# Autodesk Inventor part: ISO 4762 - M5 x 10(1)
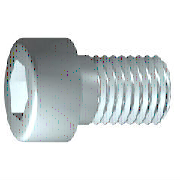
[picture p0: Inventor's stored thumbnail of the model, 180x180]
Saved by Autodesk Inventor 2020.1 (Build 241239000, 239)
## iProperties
Created: 2019-01
Part Number: ISO 4762 - M5 x 10(1)
Material: Edelstahl, 440C
Description: Innensechskantschraube
Document SubType Name: Modeling
Standard: ISO 4762
Designer: lutzd
Standard Revision: Fourth edition 2004-03-01
Standards Organization: ISO
Language: de-DE
Size Designation: M5 x 10
Categories: <MemberInstance><Categories><Category DisplayName="Verbindungselemente" InternalName="e4da775c-781d-43d5-af7c-5136215cf5a6" Mnemonic="FSTN"><Category DisplayNam
Mass: 3.37173 g
Surface Area: 4.31157 cm^2
Volume: 0.435062 cm^3
Density: 7.75 g/cm^3
Appearance: Halbpoliert
IsCustomPart: 0
Author: lutzd
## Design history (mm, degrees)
body "Solid1"
sketch "Skizze1"
  geometry: L1 (-1.167, 0)-(10, 0); L2 (10, 0)-(10, 2.5); L3 (10, 2.5)-(2, 2.5); L4 (2, 2.5)-(1.509, 2.5); L5 (1.509, 2.5)-(0, 2.5); L6 (0, 2.5)-(0, 4.25); L7 (0, 4.25)-(-5, 4.25); L8 (-5, 4.25)-(-5, 2.309); L9 (-5, 2.309)-(-2.5, 2.309); L10 (-2.5, 2.309)-(-1.167, 0); L11 (-8, 0)-(13, 0) reference; L12 (0, -0.85)-(0, 5.1) reference; L13 (2, 2.5)-(0, 2.5)
  constraints: 22 end point, 6 parallel, 2 collinear, 2 perpendicular, 1 horizontal, 1 point on line
  dimensions: "d1" = 8 distance from line of L3.end L2 (= GEL); "d2" = 0.49086 distance of L4.end L3.end (computed from GAL); "d3" = 5 distance between parallel lines of L8 L6 (= KOH); "d4" = 2.5 distance of L8.end L9.end (= INTI); "d5" = 60 deg angle of L10 L1; "d6" = 5 diameter of L3 L1 (= GD); "d7" = 5 diameter of L5 L1 (= BDM); "d8" = 4.6188 diameter of L9 L1 (= 1.1547 x SW); "d9" = 8.5 diameter of L7 L1 (= KOD); "d26" = 10 distance between parallel lines of L12 L2 (= NLG)
workplane "Work Plane1"
fillet "Fillet2" dims "d30" = 0.1 (= R)
revolve "Körper" stored, may be unused: angle "d10" = 90 deg
sketch "Skizze2"
  geometry: L1 (0, -5.95)-(0, 5.95) reference; L2 (-5.95, 0)-(5.95, 0) reference; L3 (2.309, 0)-(1.155, -2); L4 (1.155, -2)-(-1.155, -2); L5 (-1.155, -2)-(-2.309, 0); L6 (-2.309, 0)-(-1.155, 2); L7 (-1.155, 2)-(1.155, 2); L8 (1.155, 2)-(2.309, 0); 2 further points
  constraints: 12 end point, 1 coincident, 1 horizontal alignment, 1 point on line, 12 other
extrude "Loch" join sketch "Skizze2" stored distance "d11" = 10; taper "d12" = 0 deg
fillet "Rundung1" dims "d17" = 0.5 (= RR)
feature "Gewinde" dims "d13" = 8 (= GEL), "d14" = 0
chamfer "Fase1" distance "d15" = 0.49076 (= -0.5 x SPD + 0.5 x GD); stored, may be unused: second distance "d16" = 0.49076 (= GUL), angle "d27" = 45 deg
other parameters: "GD" = 5 [user parameter; used in 2 equation terms], "NLG" = 10 [user parameter; used in 1 equation term], "GEL" = 8 [user parameter; used in 2 equation terms], "KOD" = 8.5 [user parameter; used in 1 equation term], "KOH" = 5 [user parameter; used in 1 equation term], "INTI" = 2.5 [user parameter; used in 1 equation term], "GAL" = 0.49076 (= 0.61345 x PTC) [user parameter; used in 1 equation term], "GUL" = 0.49076 (= 0.61345 x PTC) [user parameter; used in 1 equation term], "BDM" = 5 (= NND) [user parameter; used in 1 equation term], "SW" = 4 [user parameter; used in 2 equation terms], "RR" = 0.5 [user parameter; used in 1 equation term], "SPD" = 4.01848 (= NND - 1.2269 x PTC) [user parameter; used in 1 equation term], "d19" = 0, "d28" = 0, "d29" = 0, "R" = 0.1 [user parameter; used in 1 equation term], "TOA" = 30 deg [user parameter], "GD1" = 4.01848 (= THREADDIA - 1.2269 x PTC) [user parameter], "THREADDIA" = 5 [user parameter; used in 1 equation term], "FAWI" = 45 deg [user parameter], "TPU" = 12.5 (computed from PTC) [user parameter], "PTC" = 0.8 [user parameter; used in 5 equation terms], "NND" = 5 [user parameter; used in 2 equation terms], "E0" = 4.62 (= 1.155 x SW) [user parameter]
